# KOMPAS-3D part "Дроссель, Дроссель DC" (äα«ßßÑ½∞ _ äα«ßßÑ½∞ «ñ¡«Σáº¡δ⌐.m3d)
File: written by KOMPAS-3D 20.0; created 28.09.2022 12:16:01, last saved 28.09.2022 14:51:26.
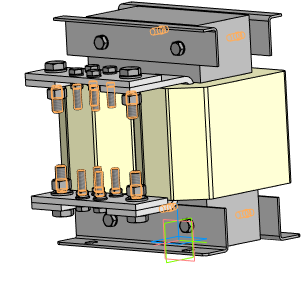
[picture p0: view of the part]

Document properties: Автор: admin; Полное имя файла: C:\Users\ceh\Desktop\Уралов\Шлюз\Дроссель _ Дроссель однофазный.m3d

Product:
- Part/product: Дроссель  | designation Дроссель DC
    Масса: 74.2568
    source file: Дроссель _ Дроссель однофазный.cdw
  - Component [standard]: Болт М10x1x45 ГОСТ Р 50790-95  | qty 8  | Масса: 0.0386; Раздел спецификации: Стандартные изделия; Рассекать на разрезах: no; source file: ..\..\..\..\..\Program Files\ASCON\KOMPAS-3D v20\Libs\PARTLib\DATA\vault\Methods\Kompas\3D\PLib_Bolt_1_ISO_1100.m3d
  - Component [standard]: Шайба 10 ГОСТ 6402-70  | qty 12  | Масса: 0.00201; Раздел спецификации: Стандартные изделия; Рассекать на разрезах: no; additional columns: 10; source file: ..\..\..\..\..\Program Files\ASCON\KOMPAS-3D v20\Libs\PARTLib\DATA\vault\Methods\Kompas\3D\PLib_Washer_2_712.m3d
  - Component [standard]: Шайба A 10.37 ГОСТ 10450-78  | qty 24  | Материал: АД1 ГОСТ 4784-97 (density 1000 kg/m3); Масса: 0.00210856; Раздел спецификации: Стандартные изделия; Рассекать на разрезах: no; source file: ..\..\..\..\..\Program Files\ASCON\KOMPAS-3D v20\Libs\PARTLib\DATA\vault\Methods\Kompas\3D\PLib_Washer_1_712.m3d
  - Component [standard]: Гайка М14-6H ГОСТ 5915-70  | qty 4  | Масса: 0.02891; Раздел спецификации: Стандартные изделия; Рассекать на разрезах: no; source file: ..\..\..\..\..\Program Files\ASCON\KOMPAS-3D v20\Libs\PARTLib\DATA\vault\Methods\Kompas\3D\PLib_Nut_OST92_900.m3d
  - Component [standard]: Шайба 14 ГОСТ 6402-70  | qty 4  | Масса: 0.00448; Раздел спецификации: Стандартные изделия; Рассекать на разрезах: no; additional columns: 14; source file: ..\..\..\..\..\Program Files\ASCON\KOMPAS-3D v20\Libs\PARTLib\DATA\vault\Methods\Kompas\3D\PLib_Washer_2_712.m3d
  - Component [standard]: Болт ГОСТ 32484.3 - М14 x 55 - HR  | qty 4
      Материал: Не определено (density 1000 kg/m3)
      Масса: 0.0127554
      Раздел спецификации: Стандартные изделия
      Рассекать на разрезах: no
      additional columns: ГОСТ 32484.3-2013
      source file: ..\..\..\..\..\Program Files\ASCON\KOMPAS-3D v20\Libs\PARTLib\DATA\vault\Methods\Kompas\3D\PLib_Bolt_1_ISO_1100.m3d
  - Component [standard]: Шайба A.14.37 ГОСТ 11371-78  | qty 8  | Материал: АД1 ГОСТ 4784-97 (density 1000 kg/m3); Масса: 0.008612; Раздел спецификации: Стандартные изделия; Рассекать на разрезах: no; source file: ..\..\..\..\..\Program Files\ASCON\KOMPAS-3D v20\Libs\PARTLib\DATA\vault\Methods\Kompas\3D\PLib_Washer_1_712.m3d
  - Body: Тело 1
      Масса: 1.08073
  - Body: Тело 2
      Масса: 70.0804
  - Body: Тело 3
      Масса: 0.833243
  - Body: Тело 4
      Масса: 0.624206
  - Body: Тело 5
      Масса: 0.624206
  - Component [standard]: Гайка М10-6H ГОСТ 15522-70  | qty 8  | Масса: 0.003416; Раздел спецификации: Стандартные изделия; Рассекать на разрезах: no; source file: ..\..\..\..\..\Program Files\ASCON\KOMPAS-3D v20\Libs\PARTLib\DATA\vault\Methods\Kompas\3D\PLib_Nut_OST92_900.m3d
  - Component [standard]: Гайка М10-6H ГОСТ 2526-70  | qty 4  | Масса: 0.003713; Раздел спецификации: Стандартные изделия; Рассекать на разрезах: no; source file: ..\..\..\..\..\Program Files\ASCON\KOMPAS-3D v20\Libs\PARTLib\DATA\vault\Methods\Kompas\3D\PLib_Nut_OST92_900.m3d
  - Component [standard]: Болт М10-6gx120 (S16) ГОСТ 7798-70  | qty 4  | Масса: 0.08372; Раздел спецификации: Стандартные изделия; Рассекать на разрезах: no; source file: ..\..\..\..\..\Program Files\ASCON\KOMPAS-3D v20\Libs\PARTLib\DATA\vault\Methods\Kompas\3D\PLib_Bolt_1_900.m3d

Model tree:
1. Эскиз:1
2. Элемент выдавливания:1
     Расстояние 1 = 255
3. Эскиз:2  (with: Элемент выдавливания:1)
4. Элемент выдавливания:2
     Расстояние 1 = 190
5. Эскиз:3  (with: Элемент выдавливания:2)
6. Элемент выдавливания:3
     Расстояние 1 = 142
7. Эскиз:4  (with: Элемент выдавливания:3)
8. Элемент выдавливания:4
     Расстояние 1 = 73
9. Эскиз:5  (with: Элемент выдавливания:4)
10. Элемент выдавливания:5
     Расстояние 1 = 255
11. Смещенная плоскость:1  (with: Элемент выдавливания:3)
     Расстояние = 63.5
12. Эскиз:6  (with: Элемент выдавливания:3)
13. Элемент выдавливания:6
     Расстояние 1 = 50
14. Смещенная плоскость:2  (with: Элемент выдавливания:3)
     Расстояние = 63.5
15. Эскиз:7  (with: Элемент выдавливания:3)
16. Элемент выдавливания:7
     Расстояние 1 = 50
17. Эскиз:8  (with: Элемент выдавливания:6)
18. Элемент выдавливания:8
     Расстояние 1 = 8
19. Эскиз:9  (with: Элемент выдавливания:6)
20. Элемент выдавливания:9
     Расстояние 1 = 8
21. Эскиз:10  (with: Элемент выдавливания:1)
22. Элемент выдавливания:10
     Расстояние 2 = 3
23. Эскиз:11  (with: Элемент выдавливания:5, Элемент выдавливания:1)
24. Элемент выдавливания:11
     Расстояние 2 = 130
25. Эскиз:12  (with: Элемент выдавливания:9, Элемент выдавливания:6, Элемент выдавливания:7)
26. Элемент выдавливания:12
27. Эскиз:13  (with: Элемент выдавливания:3)
28. Элемент выдавливания:13  (with: Элемент выдавливания:3, Элемент выдавливания:9, Элемент выдавливания:12, Элемент выдавливания:8, Элемент выдавливания:7, Элемент выдавливания:6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)  (labels: Операция выдавливания:1; Операция выдавливания:1; Операция выдавливания:1; Операция выдавливания:1)
     Расстояние 2 = 142

Referenced files in C:\Program Files\ASCON\KOMPAS-3D v20\Libs\PARTLib\DATA\vault\Methods\Kompas\3D\: PLib_Washer_1_712.m3d, PLib_Bolt_1_ISO_1100.m3d, PLib_Washer_2_712.m3d, PLib_Nut_OST92_900.m3d, PLib_Bolt_1_900.m3d
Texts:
  hole1
  hole2
  bcut1
  hcut1
  cut1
